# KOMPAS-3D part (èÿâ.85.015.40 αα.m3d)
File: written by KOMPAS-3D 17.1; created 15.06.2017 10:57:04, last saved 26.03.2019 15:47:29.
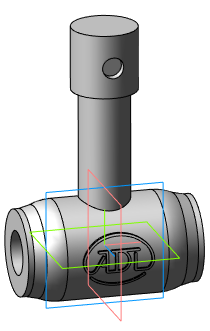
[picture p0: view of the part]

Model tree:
1. Операция без истории:2  (labels: Сталь 20  ГОСТ 1050-88)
